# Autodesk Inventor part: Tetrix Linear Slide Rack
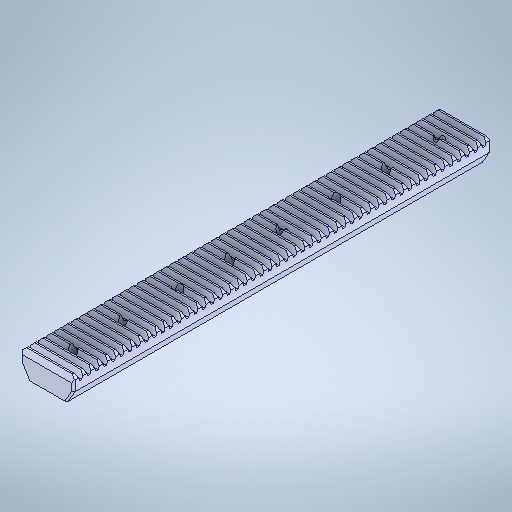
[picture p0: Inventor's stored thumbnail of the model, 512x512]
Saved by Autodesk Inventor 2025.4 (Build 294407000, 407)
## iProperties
Created: 2021-10
Part Number: Tetrix Linear Slide Rack
Material: Genérico
Document SubType Name: Modeling
Designer: usuario
Density: 1 g/cm^3
Appearance: Valor por defecto
Author: usuario
Sending System: SolidWorks 2016
Last Author: LENOVO
Last Saved: 2021-10-23
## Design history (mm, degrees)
chamfer "Chamfer2"
node "Sólido1"
